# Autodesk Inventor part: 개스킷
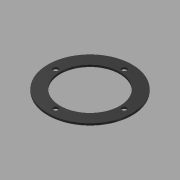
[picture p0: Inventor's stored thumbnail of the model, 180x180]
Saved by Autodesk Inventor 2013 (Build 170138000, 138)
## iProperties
Created: 2018-06
Part Number: 개스킷
Material: 고무
Document SubType Name: Modeling
Designer: G4400
Density: 0.93 g/cm^3
Mass: 2.24056 g
Surface Area: 38.1075 cm^2
Volume: 2.40921 cm^3
Author: G4400
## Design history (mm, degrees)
sketch "스케치1"
  geometry: C1 r 32.5 at (0, 0); C2 r 23 at (0, 0); 1 further point
  constraints: 2 centre point, 2 coincident
  dimensions: "d0" = 65 diameter of C1; "d1" = 46 diameter of C2
extrude "돌출1" new body sketch "스케치1" distance "d2" = 1.5; taper "d3" = 0 deg
sketch "스케치2" dims "d5" = 26.5
  geometry: C1 r 23 at (0, 0) reference; C2 r 32.5 at (0, 0) reference; 5 further points
  constraints: 2 vertical alignment, 1 coincident, 7 other
  dimensions: "d9" = 360 deg dimension on C1.centre point (0, 26.5) (derived)
hole "구멍1" sketch "스케치2" at (-26.5, 0), (0, -26.5), (26.5, 0) diameter "d11" = 4; stored, may be unused: countersink angle "d15" = 90 deg, drill point angle "d17" = 118 deg; dims "d12" = 6, "d13" = 4, "d14" = 2, "d16" = 8
node "솔리드1"
